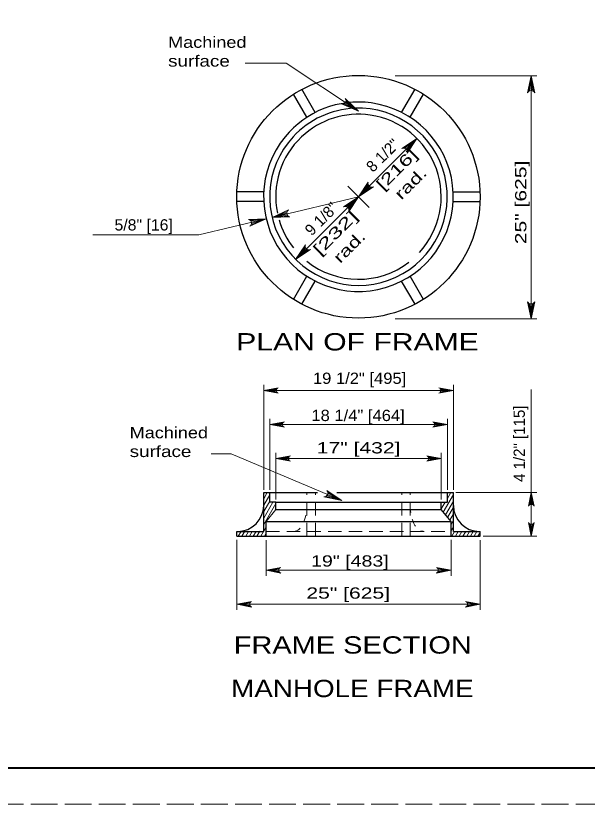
# Model space of a CAD drawing. Extents: x 339.1 to 373.1, y 1412.7 to 1456.7.
# Drawn here: x 355.85 to 363.76, y 1412.75 to 1423.68 of the extents above; entities that cross this region are included whole.
import ezdxf
from ezdxf.enums import TextEntityAlignment as Align

# ---------------------------------------------------------------- set-up
doc = ezdxf.new("R2010")
doc.units = 0
doc.header["$LTSCALE"] = 0.062
for name, pattern in [('DOTTED', [1.5, 0.3, -1.2]), ('LONG_DASHED', [7.5, 6, -1.5]), ('MEDIUM_DASHED', [4.5, 3, -1.5])]:
    doc.linetypes.add(name, pattern=pattern)
doc.layers.add('1', color=7, linetype='Continuous', lineweight=13)

msp = doc.modelspace()

# ---------------------------------------------------------------- linework, layer by layer
at = {"layer": '1'}
for p, q in [((361.10508, 1422.8495), (363.06558, 1422.8495)), ((362.95192, 1422.63375), (362.98692, 1422.8495)), ((362.96658, 1422.64192), (362.98692, 1422.8495)), ((362.98692, 1422.64567), (362.98692, 1422.8495)), ((363.00283, 1422.6435), (362.98692, 1422.8495)), ((363.0185, 1422.63625), (362.98692, 1422.8495)), ((362.98692, 1422.8495), (362.98692, 1419.48083)), ((360.41358, 1422.47975), (360.59333, 1422.36033)), ((360.42025, 1422.4935), (360.59333, 1422.36033)), ((360.42225, 1422.50992), (360.59333, 1422.36033)), ((360.38433, 1422.45958), (360.59333, 1422.36033)), ((360.39942, 1422.46617), (360.59333, 1422.36033)), ((361.22258, 1421.84733), (361.40508, 1421.9815)), ((361.23917, 1421.84375), (361.40508, 1421.9815)), ((361.25667, 1421.83333), (361.40508, 1421.9815)), ((361.26667, 1421.82142), (361.40508, 1421.9815)), ((361.27283, 1421.806), (361.40508, 1421.9815)), ((360.448, 1421.3185), (360.59458, 1421.17208)), ((360.72683, 1421.3475), (360.59458, 1421.172)), ((360.733, 1421.33208), (360.59458, 1421.172)), ((360.743, 1421.32017), (360.59458, 1421.172)), ((360.7605, 1421.30975), (360.59458, 1421.172)), ((360.77708, 1421.30617), (360.59458, 1421.172)), ((360.59458, 1421.17208), (359.398, 1420.8855)), ((359.94283, 1420.52108), (360.5945, 1421.172)), ((360.41208, 1421.03783), (360.59458, 1421.17208)), ((360.42867, 1421.03433), (360.59458, 1421.17208)), ((360.44625, 1421.02392), (360.59458, 1421.17208)), ((360.45625, 1421.01192), (360.59458, 1421.17208)), ((360.46233, 1420.9965), (360.59458, 1421.17208)), ((360.5945, 1421.172), (360.74225, 1421.02467)), ((359.6055, 1420.96692), (359.398, 1420.8855)), ((359.601, 1420.95017), (359.398, 1420.8855)), ((359.09442, 1420.84808), (359.316, 1420.86592)), ((359.10508, 1420.83592), (359.316, 1420.86592)), ((359.10833, 1420.78475), (359.316, 1420.86592)), ((359.11233, 1420.81733), (359.316, 1420.86592)), ((359.11292, 1420.8015), (359.316, 1420.86592)), ((359.60158, 1420.93433), (359.398, 1420.8855)), ((359.60883, 1420.91575), (359.398, 1420.8855)), ((359.6195, 1420.90358), (359.398, 1420.8855)), ((359.72442, 1420.303), (359.94283, 1420.52108)), ((359.85667, 1420.4785), (359.72442, 1420.303)), ((359.86283, 1420.46317), (359.72442, 1420.303)), ((359.87283, 1420.45117), (359.72442, 1420.303)), ((359.89033, 1420.44075), (359.72442, 1420.303)), ((359.90692, 1420.43725), (359.72442, 1420.303)), ((362.95525, 1419.69417), (362.98692, 1419.48083)), ((362.97092, 1419.68692), (362.98692, 1419.48083)), ((363.02183, 1419.69667), (362.98692, 1419.48083)), ((363.00717, 1419.6885), (362.98692, 1419.48083)), ((362.98692, 1419.68467), (362.98692, 1419.48083)), ((361.10508, 1419.48083), (363.06558, 1419.48083)), ((359.28142, 1417.10567), (359.28142, 1418.56383)), ((361.911, 1417.10567), (361.911, 1418.56383)), ((359.46458, 1418.50933), (359.28142, 1418.48517)), ((359.45833, 1418.49733), (359.28142, 1418.48517)), ((359.4565, 1418.48517), (359.28142, 1418.48517)), ((359.45967, 1418.46967), (359.28142, 1418.48517)), ((359.46675, 1418.45842), (359.28142, 1418.48517)), ((359.28142, 1418.48517), (361.911, 1418.48517)), ((361.72575, 1418.45842), (361.911, 1418.48517)), ((361.72783, 1418.50933), (361.911, 1418.48517)), ((361.73275, 1418.46967), (361.911, 1418.48517)), ((361.73408, 1418.49733), (361.911, 1418.48517)), ((361.736, 1418.48517), (361.911, 1418.48517)), ((362.98983, 1416.46308), (362.98983, 1418.49717)), ((359.36567, 1417.10567), (359.36567, 1418.09183)), ((359.54875, 1418.03733), (359.36567, 1418.01317)), ((359.54258, 1418.02533), (359.36567, 1418.01317)), ((359.54067, 1418.01317), (359.36567, 1418.01317)), ((359.54392, 1417.99767), (359.36567, 1418.01317)), ((359.55092, 1417.98642), (359.36567, 1418.01317)), ((359.36567, 1418.01317), (361.82675, 1418.01317)), ((361.6415, 1417.98642), (361.82675, 1418.01317)), ((361.64367, 1418.03733), (361.82675, 1418.01317)), ((361.6485, 1417.99767), (361.82675, 1418.01317)), ((361.64983, 1418.02533), (361.82675, 1418.01317)), ((361.65175, 1418.01317), (361.82675, 1418.01317)), ((361.82675, 1417.10567), (361.82675, 1418.09183)), ((359.45, 1416.97142), (359.45, 1417.61983)), ((359.63308, 1417.56533), (359.45, 1417.54117)), ((359.62692, 1417.55333), (359.45, 1417.54117)), ((361.55933, 1417.56533), (361.74242, 1417.54117)), ((361.5655, 1417.55333), (361.74242, 1417.54117)), ((361.74242, 1416.97142), (361.74242, 1417.61983)), ((359.625, 1417.54117), (359.45, 1417.54117)), ((359.62825, 1417.52567), (359.45, 1417.54117)), ((359.63525, 1417.51442), (359.45, 1417.54117)), ((359.45, 1417.54117), (361.74242, 1417.54117)), ((361.55717, 1417.51442), (361.74242, 1417.54117)), ((361.56417, 1417.52567), (361.74242, 1417.54117)), ((361.56742, 1417.54117), (361.74242, 1417.54117)), ((359.2815, 1416.98408), (359.33067, 1417.06925)), ((359.28217, 1416.89542), (359.3655, 1417.03958)), ((360.14375, 1417.01617), (360.3635, 1416.95758)), ((360.15708, 1417.02675), (360.3635, 1416.95758)), ((360.16567, 1417.03967), (360.3635, 1416.95758)), ((360.16817, 1417.07467), (360.3635, 1416.95758)), ((360.17017, 1417.05875), (360.3635, 1416.95758)), ((361.76942, 1416.79833), (361.90967, 1417.04108)), ((361.827, 1416.98792), (361.8755, 1417.07175)), ((361.94333, 1417.06917), (363.0685, 1417.06917)), ((362.9615, 1416.89433), (362.98983, 1417.06917)), ((362.97342, 1416.901), (362.98983, 1417.06917)), ((362.98983, 1416.904), (362.98983, 1417.06917)), ((363.00275, 1416.90225), (362.98983, 1417.06917)), ((363.0155, 1416.89642), (362.98983, 1417.06917)), ((359.28133, 1416.80425), (359.36592, 1416.95067)), ((359.28142, 1416.71475), (359.40808, 1416.93375)), ((359.28158, 1416.625), (359.44967, 1416.91583)), ((361.74267, 1416.84183), (361.7955, 1416.93333)), ((361.8, 1416.76142), (361.90967, 1416.95125)), ((359.31517, 1416.66508), (359.45, 1416.83342)), ((361.82967, 1416.72308), (361.91142, 1416.86467)), ((361.86008, 1416.68592), (361.91217, 1416.776)), ((361.87783, 1416.62692), (361.91192, 1416.68575)), ((359.28142, 1416.53508), (359.31508, 1416.59333)), ((361.87592, 1416.53375), (361.91, 1416.59267)), ((362.96425, 1416.63583), (362.98983, 1416.46308)), ((362.97692, 1416.63), (362.98983, 1416.46308)), ((363.01817, 1416.63783), (362.98983, 1416.46308)), ((363.00633, 1416.63125), (362.98983, 1416.46308)), ((362.98983, 1416.62817), (362.98983, 1416.46308)), ((358.92808, 1416.4625), (358.96725, 1416.53025)), ((358.98017, 1416.46292), (359.01967, 1416.53117)), ((359.03233, 1416.46325), (359.071, 1416.53008)), ((359.08467, 1416.46408), (359.12292, 1416.53025)), ((359.13633, 1416.46367), (359.17483, 1416.53017)), ((359.18808, 1416.46333), (359.22725, 1416.53108)), ((359.23983, 1416.46308), (359.27833, 1416.52992)), ((359.29167, 1416.463), (359.315, 1416.50342)), ((361.88658, 1416.46233), (361.92458, 1416.52808)), ((361.93958, 1416.46425), (361.97742, 1416.52975)), ((361.99075, 1416.463), (362.02908, 1416.52925)), ((362.043, 1416.4635), (362.08108, 1416.5295)), ((362.09492, 1416.46367), (362.1325, 1416.52867)), ((362.14675, 1416.4635), (362.18467, 1416.52925)), ((362.19825, 1416.46292), (362.23717, 1416.53025)), ((362.25025, 1416.463), (362.28133, 1416.51675)), ((362.323, 1416.46308), (363.0685, 1416.46308)), ((358.91042, 1416.41167), (358.91042, 1415.44042)), ((359.31517, 1416.40883), (359.31517, 1415.91242)), ((361.87725, 1416.4125), (361.87725, 1415.91242)), ((362.28183, 1416.40658), (362.28183, 1415.44042)), ((359.49825, 1416.01525), (359.31517, 1415.99108)), ((359.49208, 1416.00325), (359.31517, 1415.99108)), ((359.49017, 1415.99108), (359.31517, 1415.99108)), ((359.49342, 1415.97558), (359.31517, 1415.99108)), ((359.50042, 1415.96433), (359.31517, 1415.99108)), ((359.31517, 1415.99108), (361.87725, 1415.99108)), ((361.692, 1415.96433), (361.87725, 1415.99108)), ((361.69417, 1416.01525), (361.87725, 1415.99108)), ((361.699, 1415.97558), (361.87725, 1415.99108)), ((361.70033, 1416.00325), (361.87725, 1415.99108)), ((361.70225, 1415.99108), (361.87725, 1415.99108)), ((359.0935, 1415.54325), (358.91042, 1415.51908)), ((359.08733, 1415.53125), (358.91042, 1415.51908)), ((359.08542, 1415.51908), (358.91042, 1415.51908)), ((359.08867, 1415.50358), (358.91042, 1415.51908)), ((359.09567, 1415.49233), (358.91042, 1415.51908)), ((358.91042, 1415.51908), (362.28183, 1415.51908)), ((362.09658, 1415.49233), (362.28183, 1415.51908)), ((362.09875, 1415.54325), (362.28183, 1415.51908)), ((362.10358, 1415.50358), (362.28183, 1415.51908)), ((362.10492, 1415.53125), (362.28183, 1415.51908)), ((362.10683, 1415.51908), (362.28183, 1415.51908))]:
    msp.add_line(p, q, dxfattribs=at)
at = {"layer": '1', "lineweight": 25}
for p, q in [((359.87975, 1422.27408), (359.69408, 1422.59517)), ((359.99642, 1422.34142), (359.81083, 1422.6625)), ((361.19283, 1422.34142), (361.37833, 1422.6625)), ((361.30958, 1422.27408), (361.49517, 1422.59517)), ((359.2815, 1421.23925), (358.91042, 1421.23925)), ((361.90775, 1421.23925), (362.27892, 1421.23925)), ((359.2815, 1421.10458), (358.91042, 1421.10458)), ((361.90775, 1421.10458), (362.27892, 1421.10458)), ((359.69417, 1419.74883), (359.87975, 1420.06992)), ((361.49542, 1419.74892), (361.30983, 1420.07)), ((359.81083, 1419.6815), (359.99642, 1420.00258)), ((361.37883, 1419.68158), (361.19325, 1420.00267)), ((359.28142, 1416.53042), (359.28142, 1417.06917)), ((359.28142, 1417.06917), (360.0255, 1417.06917)), ((359.36567, 1416.9345), (359.36567, 1417.06917)), ((360.29458, 1417.06917), (361.911, 1417.06917)), ((361.82675, 1416.9345), (361.82675, 1417.06917)), ((361.911, 1416.53042), (361.911, 1417.06917)), ((359.45, 1416.9345), (359.36567, 1416.9345)), ((359.45, 1416.83342), (359.45, 1416.9345)), ((359.45, 1416.9345), (361.74242, 1416.9345)), ((361.74242, 1416.83342), (361.74242, 1416.9345)), ((361.74242, 1416.9345), (361.82675, 1416.9345)), ((359.45, 1416.83342), (361.74242, 1416.83342)), ((361.87725, 1416.66508), (361.74242, 1416.83342)), ((359.31517, 1416.66508), (361.87725, 1416.66508)), ((359.31517, 1416.46308), (359.31517, 1416.66508)), ((361.87725, 1416.46308), (361.87725, 1416.66508)), ((358.91042, 1416.46308), (358.91042, 1416.53042)), ((358.91042, 1416.53042), (359.28142, 1416.53042)), ((358.91042, 1416.46308), (360.87825, 1416.46308)), ((360.87825, 1416.46308), (362.28183, 1416.46308)), ((361.911, 1416.53042), (362.28183, 1416.53042)), ((362.28183, 1416.46308), (362.28183, 1416.53042))]:
    msp.add_line(p, q, dxfattribs=at)
at = {"layer": '1', "linetype": 'MEDIUM_DASHED'}
for p, q in [((359.88125, 1416.46308), (359.88125, 1417.06917)), ((359.99792, 1416.46308), (359.99792, 1417.06917)), ((361.19433, 1416.46308), (361.19433, 1417.06917)), ((361.31108, 1416.46308), (361.31108, 1417.06917)), ((359.31517, 1416.53042), (361.87725, 1416.53042))]:
    msp.add_line(p, q, dxfattribs=at)
at = {"layer": '1', "linetype": 'LONG_DASHED'}
msp.add_lwpolyline([(339.0605, 1412.7455), (373.0605, 1412.7455), (373.0605, 1434.7455), (339.0605, 1434.7455)], close=True, dxfattribs=at)
at = {"layer": '1', "lineweight": 25}
msp.add_lwpolyline([(372.5605, 1413.2455), (341.0605, 1413.2455), (341.0605, 1434.2455)], dxfattribs=at)
at = {"layer": '1', "lineweight": 40}
msp.add_lwpolyline([(341.0605, 1434.2455), (372.5605, 1434.2455), (372.5605, 1413.2455), (341.0605, 1413.2455)], close=True, dxfattribs=at)
at = {"layer": '1'}
for points in [[(360.59333, 1422.36033), (359.59375, 1423.0265), (359.02508, 1423.0265)], [(362.93692, 1422.61392), (362.98692, 1422.8495), (363.03683, 1422.61392)], [(360.35883, 1422.4595), (360.59333, 1422.36033), (360.41242, 1422.53717)], [(360.59458, 1421.17208), (360.86092, 1421.43808), (361.40508, 1421.9815)], [(361.19725, 1421.84258), (361.40508, 1421.9815), (361.26992, 1421.77792)], [(360.80242, 1421.31083), (360.59458, 1421.172), (360.72975, 1421.37558)], [(360.38683, 1421.03317), (360.59458, 1421.17208), (360.45942, 1420.96842)], [(359.64183, 1420.894), (359.398, 1420.8855), (359.62467, 1420.98983)], [(359.316, 1420.86592), (358.38167, 1420.64217), (356.9115, 1420.64217)], [(359.07208, 1420.85775), (359.316, 1420.86592), (359.08917, 1420.76183)], [(359.93225, 1420.44192), (359.72442, 1420.303), (359.85967, 1420.50658)], [(363.03683, 1419.71642), (362.98692, 1419.48083), (362.93692, 1419.71642)], [(359.48367, 1418.447), (359.28142, 1418.48517), (359.48367, 1418.52333)], [(361.70875, 1418.447), (361.911, 1418.48517), (361.70875, 1418.52333)], [(359.56792, 1417.975), (359.36567, 1418.01317), (359.56792, 1418.05133)], [(361.6245, 1417.975), (361.82675, 1418.01317), (361.6245, 1418.05133)], [(360.3635, 1416.95758), (358.83017, 1417.60783), (358.55217, 1417.60783)], [(359.65225, 1417.503), (359.45, 1417.54117), (359.65225, 1417.57933)], [(361.54017, 1417.503), (361.74242, 1417.54117), (361.54017, 1417.57933)], [(360.155, 1417.09558), (360.3635, 1416.95758), (360.11475, 1417.00933)], [(362.94942, 1416.87833), (362.98983, 1417.06917), (363.03033, 1416.87833)], [(363.03033, 1416.65392), (362.98983, 1416.46308), (362.94942, 1416.65392)], [(359.51742, 1415.95292), (359.31517, 1415.99108), (359.51742, 1416.02925)], [(361.675, 1415.95292), (361.87725, 1415.99108), (361.675, 1416.02925)], [(359.11267, 1415.48092), (358.91042, 1415.51908), (359.11267, 1415.55725)], [(362.07958, 1415.48092), (362.28183, 1415.51908), (362.07958, 1415.55725)]]:
    msp.add_lwpolyline(points, dxfattribs=at)
at = {"layer": '1', "lineweight": 25}
msp.add_ellipse((360.5946, 1421.1719), major_axis=(-1.68562, 0), ratio=0.998785, dxfattribs=at)
at = {"layer": '1'}
for centre, major_axis, start_param, end_param in [((362.98694, 1422.59491), (0.0539, 0), 0.38550522, 2.75611836), ((360.36886, 1422.50954), (0.04864, -0.02322), 4.94849984, 7.31911298), ((361.21977, 1421.7964), (0.0539, 0), 5.91182162, 8.28243476), ((360.77989, 1421.35709), (-0.0539, 0), 5.9117965, 8.28240964), ((359.65225, 1420.94651), (0.02689, 0.04671), 1.11399857, 3.48461171), ((360.40931, 1420.98695), (0.0539, 0), 5.9117932, 8.28240634), ((359.06165, 1420.8052), (-0.02693, -0.04669), 1.11386035, 3.48447349), ((359.90974, 1420.48812), (-0.0539, 0), 5.91178976, 8.2824029), ((362.98682, 1419.73546), (-0.0539, 0), 0.38550522, 2.75611836), ((359.50004, 1418.48519), (-0.04366, 0), 5.0978942, 7.46850734), ((361.69239, 1418.48519), (0.04366, 0), 5.09786327, 7.46847641), ((359.58428, 1418.01319), (-0.04366, 0), 5.0978942, 7.46850734), ((361.60816, 1418.01319), (0.04366, 0), 5.09786327, 7.46847641), ((359.6686, 1417.54119), (-0.04366, 0), 5.0978942, 7.46850734), ((361.52383, 1417.54119), (0.04366, 0), 5.09786327, 7.46847641), ((360.11638, 1417.06004), (-0.0539, 0), 1.54205371, 3.91266685), ((362.98989, 1416.86291), (0.04366, 0), 0.38550522, 2.75611836), ((362.9898, 1416.6693), (-0.04366, 0), 0.38550522, 2.75611836), ((359.53375, 1415.99111), (-0.04366, 0), 5.0978942, 7.46850734), ((361.65868, 1415.99111), (0.04366, 0), 5.09786327, 7.46847641), ((359.12902, 1415.5191), (-0.04366, 0), 5.0978942, 7.46850734), ((362.06323, 1415.5191), (0.04366, 0), 5.09786327, 7.46847641)]:
    msp.add_ellipse(centre, major_axis=major_axis, ratio=0.943396, start_param=start_param, end_param=end_param, dxfattribs=at)
at = {"layer": '1', "lineweight": 25}
for centre, major_axis, start_param, end_param in [((360.5946, 1421.1719), (-1.31479, 0), 5.59566118, 10.86073408), ((360.5946, 1421.1719), (-1.31479, 0), 4.57754853, 5.59566118), ((360.5946, 1421.1719), (-1.23051, 0), 5.53954153, 11.03819116), ((360.5946, 1421.1719), (-1.23051, 0), 4.75500585, 5.53954143), ((360.5946, 1421.1719), (-1.14623, 0), 4.56944753, 5.47193843), ((360.5946, 1421.1719), (-1.14623, 0), 2.40085645, 4.56944763), ((360.5946, 1421.1719), (-1.14623, 0), 5.47193848, 6.48238958), ((360.5946, 1421.1719), (-1.14623, 0), 0.28203949, 0.66810215), ((360.5946, 1421.1719), (-1.14623, 0), 0.89600836, 2.22627199), ((358.92183, 1416.88957), (0.3596, 0), 4.71238903, 6.28318531), ((362.27061, 1416.88957), (0.3596, 0), 3.14159275, 4.71238903)]:
    msp.add_ellipse(centre, major_axis=major_axis, ratio=0.998785, start_param=start_param, end_param=end_param, dxfattribs=at)
at = {"layer": '1', "linetype": 'DOTTED'}
for centre, start_param, end_param in [((359.69938, 1416.88957), 6.28318531, 7.85398159), ((361.4909, 1416.89128), 4.71238903, 6.28318531)]:
    msp.add_ellipse(centre, major_axis=(0, -0.35916), ratio=0.500608, start_param=start_param, end_param=end_param, dxfattribs=at)

# ---------------------------------------------------------------- texts
at = {"layer": '1'}
for s, height, width, p in [('Machined', 0.156, 1.2, (357.95708, 1423.23792)), ('surface', 0.156, 1.25, (357.95708, 1422.97725)), ('PLAN OF FRAME', 0.24, 1.3, (358.90025, 1419.04)), ('19 1/2" [495]', 0.156, 1.1, (359.96367, 1418.57625)), ('18 1/4" [464]', 0.156, 1.1, (359.94225, 1418.06075)), ('Machined', 0.156, 1.2, (357.42433, 1417.822)), ('17" [432] ', 0.156, 1.4, (360.01717, 1417.61183)), ('surface', 0.156, 1.25, (357.42433, 1417.56133)), ('19" [483]', 0.156, 1.3, (359.93767, 1416.04217)), ('25" [625]', 0.156, 1.4, (359.87275, 1415.59675)), ('FRAME SECTION', 0.24, 1.25, (358.86667, 1414.83483)), ('MANHOLE FRAME', 0.24, 1.2, (358.83083, 1414.23117))]:
    msp.add_text(s, height=height, dxfattribs=dict(at, width=width)).set_placement(p)
for s, p in [('8 1/2"', (360.98588, 1421.69152)), ('9 1/8"', (360.13588, 1420.8106))]:
    msp.add_text(s, height=0.156, rotation=44.965, dxfattribs=at).set_placement(p, align=Align.CENTER)
for s, width, p in [('[216]', 1.5, (361.17946, 1421.49762)), ('rad.', 1.45, (361.37317, 1421.30374)), ('[232]', 1.65, (360.32946, 1420.61675)), ('rad.', 1.45, (360.52317, 1420.42282))]:
    msp.add_text(s, height=0.156, rotation=44.965, dxfattribs=dict(at, width=width)).set_placement(p, align=Align.CENTER)
at = {"layer": '1', "width": 1.4}
msp.add_text('25" [625]', height=0.156, rotation=90, dxfattribs=at).set_placement((362.92133, 1420.51392))
at = {"layer": '1', "width": 1.05}
msp.add_text('5/8" [16]', height=0.156, dxfattribs=at).set_placement((357.61833, 1420.70392), align=Align.CENTER)
at = {"layer": '1'}
msp.add_text('4 1/2" [115]', height=0.156, rotation=90, dxfattribs=at).set_placement((362.9005, 1417.21608))

doc.saveas('drawing.dxf')
